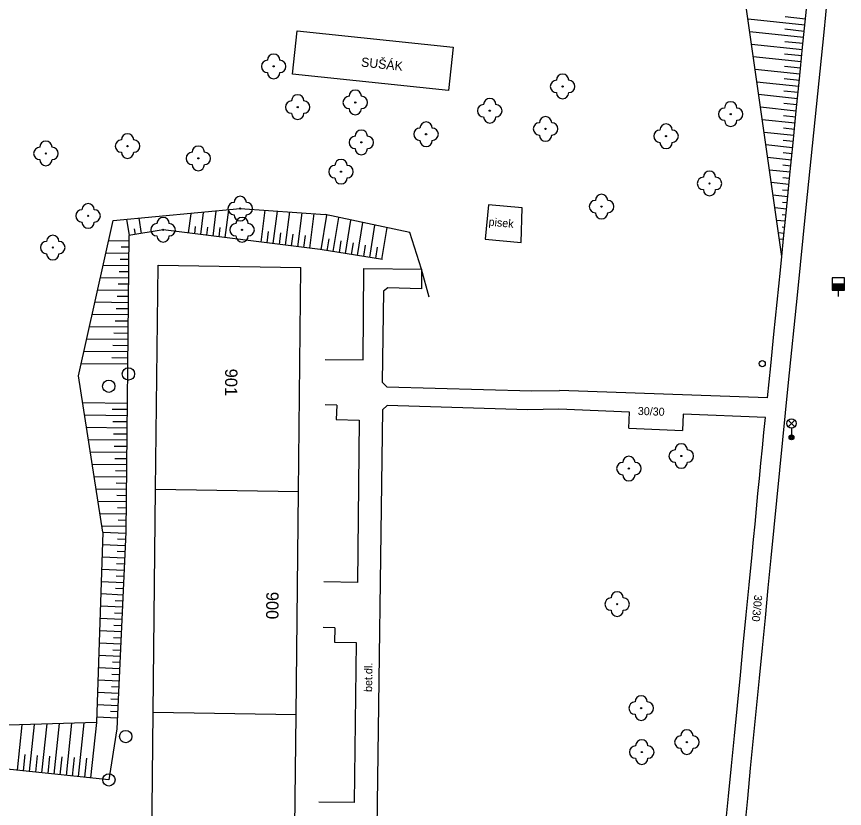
# Model space of a CAD drawing. Extents: x -539244 to -537359, y -1183785 to -1181851.
# Drawn here: x -537476 to -537408.7, y -1182005.8 to -1181941.5 of the extents above; entities that cross this region are included whole.
import ezdxf

# ---------------------------------------------------------------- set-up
doc = ezdxf.new("R2010")
doc.units = 0
for name, color, linetype in [('Vrstva 10', 7, 'Continuous'), ('Vrstva 11', 7, 'Continuous'), ('Vrstva 14', 7, 'Continuous'), ('Vrstva 15', 7, 'Continuous'), ('Vrstva 22', 7, 'Continuous'), ('Vrstva 27', 7, 'Continuous'), ('Vrstva 28', 7, 'Continuous'), ('Vrstva 33', 7, 'Continuous'), ('Vrstva 40', 7, 'Continuous'), ('Vrstva 41', 7, 'Continuous'), ('Vrstva 47', 7, 'Continuous'), ('Vrstva 5', 7, 'Continuous')]:
    doc.layers.add(name, color=color, linetype=linetype)

msp = doc.modelspace()

# ---------------------------------------------------------------- linework, layer by layer
at = {"layer": 'Vrstva 10'}
for p, q in [((-537453.538, -1181946.13), (-537453.17, -1181942.63)), ((-537453.17, -1181942.63), (-537440.512, -1181943.96)), ((-537440.512, -1181943.96), (-537440.88, -1181947.46)), ((-537440.88, -1181947.46), (-537453.538, -1181946.13)), ((-537437.632, -1181956.756), (-537437.89, -1181959.55)), ((-537434.89, -1181957.01), (-537437.632, -1181956.756)), ((-537434.97, -1181959.82), (-537434.89, -1181957.01)), ((-537437.89, -1181959.55), (-537434.97, -1181959.82))]:
    msp.add_line(p, q, dxfattribs=at)
at = {"layer": 'Vrstva 11'}
for p, q in [((-537410.375, -1181942.743), (-537409.65, -1181935.632)), ((-537411.099, -1181949.854), (-537410.375, -1181942.743)), ((-537411.82, -1181956.965), (-537411.099, -1181949.854)), ((-537412.538, -1181964.077), (-537411.82, -1181956.965)), ((-537447.8, -1181969.35), (-537447.76, -1181961.92)), ((-537446.15, -1181963.76), (-537446.26, -1181971.15)), ((-537413.252, -1181971.189), (-537412.538, -1181964.077)), ((-537450.886, -1181969.323), (-537447.8, -1181969.35)), ((-537446.26, -1181971.15), (-537445.88, -1181971.54)), ((-537413.961, -1181978.302), (-537413.252, -1181971.189)), ((-537445.88, -1181971.54), (-537434.11, -1181971.85)), ((-537434.11, -1181971.85), (-537431.866, -1181971.823)), ((-537414.96, -1181972.42), (-537431.866, -1181971.823)), ((-537449.95, -1181973.02), (-537450.908, -1181973.007)), ((-537449.95, -1181973.02), (-537449.99, -1181974.19)), ((-537445.85, -1181973.06), (-537446.25, -1181973.4)), ((-537434.47, -1181973.4), (-537445.85, -1181973.06)), ((-537446.25, -1181973.4), (-537446.83, -1182017.13)), ((-537431.926, -1181973.356), (-537434.47, -1181973.4)), ((-537426.17, -1181973.58), (-537431.926, -1181973.356)), ((-537426.221, -1181974.902), (-537426.17, -1181973.58)), ((-537421.829, -1181973.749), (-537421.88, -1181975.07)), ((-537415.14, -1181974.01), (-537421.829, -1181973.749)), ((-537449.99, -1181974.19), (-537448.13, -1181974.23)), ((-537448.13, -1181974.23), (-537448.28, -1181987.41)), ((-537415.26, -1181975.248), (-537415.14, -1181974.01)), ((-537426.221, -1181974.902), (-537421.88, -1181975.07)), ((-537414.664, -1181985.415), (-537413.961, -1181978.302)), ((-537448.28, -1181987.41), (-537451.004, -1181987.381)), ((-537450.124, -1181991.09), (-537451.057, -1181991.077)), ((-537450.124, -1181991.09), (-537450.14, -1181992.26)), ((-537450.14, -1181992.26), (-537448.369, -1181992.284)), ((-537448.369, -1181992.284), (-537448.542, -1182005.289)), ((-537448.542, -1182005.289), (-537451.42, -1182005.258))]:
    msp.add_line(p, q, dxfattribs=at)
for points in [[(-537412.114, -1181943.958), (-537411.854, -1181941.371), (-537411.64, -1181939.32), (-537411.594, -1181938.783), (-537411.334, -1181936.196), (-537411.073, -1181933.609)], [(-537413.15, -1181954.308), (-537412.892, -1181951.72), (-537412.633, -1181949.133), (-537412.374, -1181946.545), (-537412.114, -1181943.958)], [(-537414.184, -1181964.658), (-537413.926, -1181962.07), (-537413.813, -1181960.94), (-537413.667, -1181959.483), (-537413.409, -1181956.895), (-537413.15, -1181954.308)], [(-537447.76, -1181961.92), (-537443.06, -1181961.98), (-537443.08, -1181963.58), (-537445.81, -1181963.5), (-537446.15, -1181963.76)], [(-537414.96, -1181972.42), (-537414.701, -1181969.833), (-537414.443, -1181967.245), (-537414.184, -1181964.658)], [(-537416.223, -1181985.156), (-537416.103, -1181983.918), (-537415.982, -1181982.679), (-537415.862, -1181981.441), (-537415.742, -1181980.202), (-537415.621, -1181978.964), (-537415.501, -1181977.725), (-537415.381, -1181976.487), (-537415.26, -1181975.248)], [(-537416.461, -1181987.607), (-537416.223, -1181985.156)], [(-537414.904, -1181987.857), (-537414.664, -1181985.415)], [(-537417.413, -1181997.41), (-537417.175, -1181994.959), (-537416.937, -1181992.509), (-537416.699, -1181990.058), (-537416.461, -1181987.607)], [(-537415.862, -1181997.623), (-537415.623, -1181995.182), (-537415.384, -1181992.74), (-537415.144, -1181990.298), (-537414.904, -1181987.857)], [(-537417.652, -1181999.861), (-537417.413, -1181997.41)], [(-537416.1, -1182000.065), (-537415.862, -1181997.623)], [(-537418.611, -1182009.664), (-537418.372, -1182007.213), (-537418.132, -1182004.762), (-537417.892, -1182002.312), (-537417.652, -1181999.861)], [(-537417.048, -1182009.833), (-537416.811, -1182007.391), (-537416.574, -1182004.949), (-537416.337, -1182002.507), (-537416.1, -1182000.065)]]:
    msp.add_lwpolyline(points, dxfattribs=at)
at = {"layer": 'Vrstva 14'}
for p, q in [((-537413.813, -1181960.94), (-537416.94, -1181939.02)), ((-537468.12, -1181958.03), (-537457.8, -1181957.06)), ((-537457.8, -1181957.06), (-537450.9, -1181957.53)), ((-537444.02, -1181958.99), (-537450.9, -1181957.53)), ((-537470.93, -1181970.63), (-537468.12, -1181958.03)), ((-537464.06, -1181958.78), (-537466.836, -1181959.236)), ((-537451.3, -1181960.39), (-537464.06, -1181958.78)), ((-537466.836, -1181959.236), (-537467.08, -1181983.34)), ((-537446.25, -1181961.2), (-537451.3, -1181960.39)), ((-537468.95, -1181983.33), (-537470.93, -1181970.63)), ((-537468.95, -1181983.33), (-537469.48, -1181998.78)), ((-537467.08, -1181983.34), (-537467.81, -1181999.3)), ((-537469.48, -1181998.78), (-537478.65, -1181999.07)), ((-537467.81, -1181999.3), (-537468.46, -1182003.45)), ((-537468.46, -1182003.45), (-537478.76, -1182002.37))]:
    msp.add_line(p, q, dxfattribs=at)
msp.add_lwpolyline([(-537442.46, -1181964.24), (-537443.06, -1181961.98), (-537444.02, -1181958.99)], dxfattribs=at)
at = {"layer": 'Vrstva 15'}
for p, q in [((-537413.545, -1181941.469), (-537411.882, -1181941.644)), ((-537416.552, -1181941.656), (-537411.932, -1181942.141)), ((-537416.399, -1181942.678), (-537412.032, -1181943.137)), ((-537413.559, -1181942.473), (-537411.982, -1181942.639)), ((-537413.573, -1181943.477), (-537412.081, -1181943.634)), ((-537416.273, -1181943.696), (-537412.131, -1181944.132)), ((-537416.127, -1181944.717), (-537412.231, -1181945.127)), ((-537413.588, -1181944.481), (-537412.181, -1181944.629)), ((-537413.602, -1181945.485), (-537412.281, -1181945.624)), ((-537415.982, -1181945.739), (-537412.33, -1181946.122)), ((-537415.836, -1181946.759), (-537412.43, -1181947.117)), ((-537413.616, -1181946.489), (-537412.38, -1181946.62)), ((-537413.63, -1181947.493), (-537412.48, -1181947.614)), ((-537415.69, -1181947.78), (-537412.53, -1181948.112)), ((-537415.545, -1181948.8), (-537412.629, -1181949.107)), ((-537413.645, -1181948.497), (-537412.579, -1181948.61)), ((-537413.659, -1181949.501), (-537412.679, -1181949.604)), ((-537415.399, -1181949.821), (-537412.729, -1181950.102)), ((-537415.253, -1181950.842), (-537412.828, -1181951.097)), ((-537413.673, -1181950.505), (-537412.779, -1181950.6)), ((-537413.688, -1181951.509), (-537412.878, -1181951.594)), ((-537415.108, -1181951.863), (-537412.928, -1181952.092)), ((-537414.962, -1181952.884), (-537413.028, -1181953.087)), ((-537413.702, -1181952.513), (-537412.978, -1181952.59)), ((-537413.716, -1181953.517), (-537413.077, -1181953.584)), ((-537414.817, -1181953.905), (-537413.127, -1181954.082)), ((-537414.671, -1181954.925), (-537413.227, -1181955.077)), ((-537413.73, -1181954.522), (-537413.177, -1181954.58)), ((-537413.745, -1181955.526), (-537413.277, -1181955.574)), ((-537414.525, -1181955.946), (-537413.326, -1181956.073)), ((-537414.38, -1181956.967), (-537413.426, -1181957.067)), ((-537413.759, -1181956.53), (-537413.376, -1181956.57)), ((-537461.82, -1181957.471), (-537462.017, -1181959.038)), ((-537460.799, -1181957.367), (-537461.025, -1181959.163)), ((-537459.778, -1181957.262), (-537460.033, -1181959.288)), ((-537458.756, -1181957.158), (-537459.041, -1181959.413)), ((-537455.801, -1181957.196), (-537456.127, -1181959.781)), ((-537454.802, -1181957.264), (-537455.135, -1181959.906)), ((-537453.803, -1181957.332), (-537454.143, -1181960.031)), ((-537452.803, -1181957.4), (-537453.151, -1181960.156)), ((-537451.804, -1181957.468), (-537452.159, -1181960.282)), ((-537450.8, -1181957.588), (-537451.251, -1181960.398)), ((-537413.773, -1181957.534), (-537413.476, -1181957.564)), ((-537467.04, -1181957.925), (-537466.824, -1181959.234)), ((-537466.041, -1181957.832), (-537465.838, -1181959.072)), ((-537449.82, -1181957.789), (-537450.264, -1181960.556)), ((-537448.839, -1181957.99), (-537449.276, -1181960.715)), ((-537447.859, -1181958.191), (-537448.289, -1181960.873)), ((-537446.878, -1181958.392), (-537447.302, -1181961.031)), ((-537414.234, -1181957.988), (-537413.526, -1181958.063)), ((-537466.404, -1181958.707), (-537466.331, -1181959.153)), ((-537461.447, -1181958.512), (-537461.521, -1181959.1)), ((-537460.445, -1181958.557), (-537460.529, -1181959.225)), ((-537459.443, -1181958.601), (-537459.537, -1181959.351)), ((-537455.516, -1181958.929), (-537455.631, -1181959.843)), ((-537454.521, -1181959.034), (-537454.639, -1181959.969)), ((-537445.898, -1181958.593), (-537446.314, -1181961.19)), ((-537414.088, -1181959.009), (-537413.625, -1181959.057)), ((-537413.787, -1181958.538), (-537413.575, -1181958.56)), ((-537468.482, -1181959.654), (-537466.84, -1181959.671)), ((-537453.527, -1181959.139), (-537453.647, -1181960.094)), ((-537452.532, -1181959.244), (-537452.655, -1181960.219)), ((-537450.601, -1181959.501), (-537450.757, -1181960.477)), ((-537449.616, -1181959.674), (-537449.77, -1181960.635)), ((-537414.015, -1181959.525), (-537413.674, -1181959.552)), ((-537467.457, -1181960.165), (-537466.845, -1181960.171)), ((-537448.631, -1181959.848), (-537448.783, -1181960.794)), ((-537447.646, -1181960.021), (-537447.795, -1181960.952)), ((-537446.661, -1181960.194), (-537446.808, -1181961.111)), ((-537468.705, -1181960.652), (-537466.851, -1181960.671)), ((-537468.927, -1181961.65), (-537466.861, -1181961.671)), ((-537467.542, -1181961.164), (-537466.856, -1181961.171)), ((-537467.626, -1181962.163), (-537466.866, -1181962.171)), ((-537469.15, -1181962.648), (-537466.871, -1181962.671)), ((-537469.372, -1181963.645), (-537466.881, -1181963.671)), ((-537467.711, -1181963.162), (-537466.876, -1181963.171)), ((-537467.795, -1181964.161), (-537466.886, -1181964.171)), ((-537469.595, -1181964.643), (-537466.891, -1181964.671)), ((-537467.88, -1181965.161), (-537466.896, -1181965.171)), ((-537469.817, -1181965.641), (-537466.901, -1181965.671)), ((-537467.964, -1181966.16), (-537466.906, -1181966.171)), ((-537470.04, -1181966.639), (-537466.911, -1181966.67)), ((-537468.049, -1181967.159), (-537466.916, -1181967.17)), ((-537470.262, -1181967.637), (-537466.921, -1181967.67)), ((-537468.133, -1181968.158), (-537466.926, -1181968.17)), ((-537470.485, -1181968.634), (-537466.932, -1181968.67)), ((-537468.217, -1181969.157), (-537466.937, -1181969.17)), ((-537470.707, -1181969.632), (-537466.942, -1181969.67)), ((-537470.59, -1181972.813), (-537466.974, -1181972.849)), ((-537470.434, -1181973.815), (-537466.984, -1181973.849)), ((-537468.201, -1181973.337), (-537466.979, -1181973.349)), ((-537468.147, -1181974.338), (-537466.989, -1181974.349)), ((-537470.277, -1181974.816), (-537466.994, -1181974.849)), ((-537470.121, -1181975.818), (-537467.004, -1181975.849)), ((-537468.094, -1181975.338), (-537466.999, -1181975.349)), ((-537468.04, -1181976.339), (-537467.009, -1181976.349)), ((-537469.965, -1181976.819), (-537467.014, -1181976.849)), ((-537469.809, -1181977.821), (-537467.024, -1181977.849)), ((-537467.987, -1181977.339), (-537467.019, -1181977.349)), ((-537467.933, -1181978.34), (-537467.029, -1181978.349)), ((-537469.653, -1181978.823), (-537467.035, -1181978.849)), ((-537469.497, -1181979.825), (-537467.045, -1181979.849)), ((-537467.88, -1181979.341), (-537467.04, -1181979.349)), ((-537467.826, -1181980.341), (-537467.05, -1181980.349)), ((-537469.34, -1181980.826), (-537467.055, -1181980.849)), ((-537469.184, -1181981.827), (-537467.065, -1181981.849)), ((-537467.773, -1181981.342), (-537467.06, -1181981.349)), ((-537467.719, -1181982.342), (-537467.07, -1181982.349)), ((-537469.028, -1181982.829), (-537467.075, -1181982.849)), ((-537468.95, -1181983.33), (-537467.083, -1181983.415)), ((-537467.758, -1181983.885), (-537467.106, -1181983.915)), ((-537468.984, -1181984.329), (-537467.129, -1181984.414)), ((-537469.019, -1181985.329), (-537467.175, -1181985.413)), ((-537467.799, -1181984.884), (-537467.152, -1181984.914)), ((-537467.841, -1181985.883), (-537467.198, -1181985.913)), ((-537469.053, -1181986.328), (-537467.221, -1181986.412)), ((-537469.087, -1181987.328), (-537467.266, -1181987.411)), ((-537467.883, -1181986.882), (-537467.243, -1181986.912)), ((-537467.924, -1181987.882), (-537467.289, -1181987.911)), ((-537469.121, -1181988.327), (-537467.312, -1181988.41)), ((-537469.156, -1181989.327), (-537467.358, -1181989.409)), ((-537467.966, -1181988.881), (-537467.335, -1181988.91)), ((-537468.008, -1181989.88), (-537467.38, -1181989.909)), ((-537469.19, -1181990.326), (-537467.403, -1181990.408)), ((-537469.224, -1181991.326), (-537467.449, -1181991.407)), ((-537468.049, -1181990.879), (-537467.426, -1181990.908)), ((-537468.091, -1181991.878), (-537467.472, -1181991.906)), ((-537469.259, -1181992.325), (-537467.495, -1181992.406)), ((-537469.293, -1181993.325), (-537467.54, -1181993.405)), ((-537468.133, -1181992.877), (-537467.518, -1181992.905)), ((-537468.175, -1181993.876), (-537467.563, -1181993.904)), ((-537469.327, -1181994.324), (-537467.586, -1181994.404)), ((-537469.361, -1181995.324), (-537467.632, -1181995.403)), ((-537468.216, -1181994.876), (-537467.609, -1181994.903)), ((-537468.258, -1181995.875), (-537467.655, -1181995.902)), ((-537469.396, -1181996.323), (-537467.677, -1181996.402)), ((-537469.43, -1181997.323), (-537467.723, -1181997.401)), ((-537468.3, -1181996.874), (-537467.7, -1181996.901)), ((-537468.341, -1181997.873), (-537467.746, -1181997.9)), ((-537469.48, -1181998.78), (-537469.953, -1182003.293)), ((-537469.464, -1181998.322), (-537467.769, -1181998.4)), ((-537475.533, -1181998.971), (-537475.921, -1182002.668)), ((-537474.524, -1181998.94), (-537474.926, -1182002.772)), ((-537473.515, -1181998.908), (-537473.931, -1182002.876)), ((-537472.506, -1181998.876), (-537472.937, -1182002.981)), ((-537471.498, -1181998.844), (-537471.942, -1182003.085)), ((-537470.489, -1181998.812), (-537470.948, -1182003.189)), ((-537475.285, -1182001.402), (-537475.423, -1182002.72)), ((-537474.286, -1182001.459), (-537474.429, -1182002.824)), ((-537473.286, -1182001.516), (-537473.434, -1182002.928)), ((-537472.286, -1182001.572), (-537472.44, -1182003.033)), ((-537471.287, -1182001.629), (-537471.445, -1182003.137)), ((-537470.287, -1182001.685), (-537470.451, -1182003.241))]:
    msp.add_line(p, q, dxfattribs=at)
at = {"layer": 'Vrstva 22'}
for centre in [(-537455.08, -1181945.51), (-537431.61, -1181947.14), (-537453.13, -1181948.82), (-537448.45, -1181948.44), (-537437.53, -1181949.11), (-537417.96, -1181949.39), (-537442.7, -1181951.02), (-537433, -1181950.59), (-537447.96, -1181951.68), (-537423.21, -1181951.18), (-537466.95, -1181951.98), (-537473.58, -1181952.58), (-537461.2, -1181952.98), (-537449.61, -1181954.06), (-537419.68, -1181955.02), (-537457.8, -1181957.06), (-537428.45, -1181956.9), (-537470.15, -1181957.65), (-537464.06, -1181958.78), (-537457.65, -1181958.78), (-537473.02, -1181960.22), (-537421.97, -1181977.15), (-537426.23, -1181978.17), (-537427.18, -1181989.18), (-537425.23, -1181997.62), (-537421.52, -1182000.38), (-537425.18, -1182001.19)]:
    msp.add_circle(centre, 0.05, dxfattribs=at)
for centre, start, end in [((-537455.08, -1181945.01), 0, 180), ((-537455.58, -1181945.51), 90, 270), ((-537454.58, -1181945.51), 270, 90), ((-537455.08, -1181946.01), 180, 0), ((-537431.61, -1181946.64), 0, 180), ((-537432.11, -1181947.14), 90, 270), ((-537431.11, -1181947.14), 270, 90), ((-537448.45, -1181947.94), 0, 180), ((-537431.61, -1181947.64), 180, 0), ((-537453.63, -1181948.82), 90, 270), ((-537453.13, -1181948.32), 0, 180), ((-537452.63, -1181948.82), 270, 90), ((-537448.95, -1181948.44), 90, 270), ((-537447.95, -1181948.44), 270, 90), ((-537437.53, -1181948.61), 0, 180), ((-537448.45, -1181948.94), 180, 0), ((-537438.03, -1181949.11), 90, 270), ((-537437.03, -1181949.11), 270, 90), ((-537418.46, -1181949.39), 90, 270), ((-537417.96, -1181948.89), 0, 180), ((-537417.46, -1181949.39), 270, 90), ((-537453.13, -1181949.32), 180, 0), ((-537437.53, -1181949.61), 180, 0), ((-537433, -1181950.09), 0, 180), ((-537442.7, -1181950.52), 0, 180), ((-537433.5, -1181950.59), 90, 270), ((-537432.5, -1181950.59), 270, 90), ((-537423.21, -1181950.68), 0, 180), ((-537417.96, -1181949.89), 180, 0), ((-537466.95, -1181951.48), 0, 180), ((-537447.96, -1181951.18), 0, 180), ((-537443.2, -1181951.02), 90, 270), ((-537442.2, -1181951.02), 270, 90), ((-537423.71, -1181951.18), 90, 270), ((-537422.71, -1181951.18), 270, 90), ((-537473.58, -1181952.08), 0, 180), ((-537467.45, -1181951.98), 90, 270), ((-537466.45, -1181951.98), 270, 90), ((-537448.46, -1181951.68), 90, 270), ((-537447.46, -1181951.68), 270, 90), ((-537442.7, -1181951.52), 180, 0), ((-537433, -1181951.09), 180, 0), ((-537423.21, -1181951.68), 180, 0), ((-537474.08, -1181952.58), 90, 270), ((-537473.08, -1181952.58), 270, 90), ((-537461.2, -1181952.48), 0, 180), ((-537447.96, -1181952.18), 180, 0), ((-537466.95, -1181952.48), 180, 0), ((-537461.7, -1181952.98), 90, 270), ((-537460.7, -1181952.98), 270, 90), ((-537449.61, -1181953.56), 0, 180), ((-537473.58, -1181953.08), 180, 0), ((-537461.2, -1181953.48), 180, 0), ((-537450.11, -1181954.06), 90, 270), ((-537449.11, -1181954.06), 270, 90), ((-537419.68, -1181954.52), 0, 180), ((-537449.61, -1181954.56), 180, 0), ((-537420.18, -1181955.02), 90, 270), ((-537419.18, -1181955.02), 270, 90), ((-537419.68, -1181955.52), 180, 0), ((-537457.8, -1181956.56), 0, 180), ((-537428.95, -1181956.9), 90, 270), ((-537428.45, -1181956.4), 0, 180), ((-537427.95, -1181956.9), 270, 90), ((-537470.15, -1181957.15), 0, 180), ((-537458.3, -1181957.06), 90, 270), ((-537457.3, -1181957.06), 270, 90), ((-537470.65, -1181957.65), 90, 270), ((-537469.65, -1181957.65), 270, 90), ((-537464.06, -1181958.28), 0, 180), ((-537457.8, -1181957.56), 180, 0), ((-537457.65, -1181958.28), 0, 180), ((-537428.45, -1181957.4), 180, 0), ((-537470.15, -1181958.15), 180, 0), ((-537464.56, -1181958.78), 90, 270), ((-537463.56, -1181958.78), 270, 90), ((-537458.15, -1181958.78), 90, 270), ((-537457.15, -1181958.78), 270, 90), ((-537473.52, -1181960.22), 90, 270), ((-537473.02, -1181959.72), 0, 180), ((-537472.52, -1181960.22), 270, 90), ((-537464.06, -1181959.28), 180, 0), ((-537457.65, -1181959.28), 180, 0), ((-537473.02, -1181960.72), 180, 0), ((-537421.97, -1181976.65), 0, 180), ((-537426.23, -1181977.67), 0, 180), ((-537422.47, -1181977.15), 90, 270), ((-537421.47, -1181977.15), 270, 90), ((-537426.73, -1181978.17), 90, 270), ((-537425.73, -1181978.17), 270, 90), ((-537421.97, -1181977.65), 180, 0), ((-537426.23, -1181978.67), 180, 0), ((-537427.68, -1181989.18), 90, 270), ((-537427.18, -1181988.68), 0, 180), ((-537426.68, -1181989.18), 270, 90), ((-537427.18, -1181989.68), 180, 0), ((-537425.23, -1181997.12), 0, 180), ((-537425.73, -1181997.62), 90, 270), ((-537424.73, -1181997.62), 270, 90), ((-537425.23, -1181998.12), 180, 0), ((-537421.52, -1181999.88), 0, 180), ((-537422.02, -1182000.38), 90, 270), ((-537421.02, -1182000.38), 270, 90), ((-537425.68, -1182001.19), 90, 270), ((-537425.18, -1182000.69), 0, 180), ((-537424.68, -1182001.19), 270, 90), ((-537421.52, -1182000.88), 180, 0), ((-537425.18, -1182001.69), 180, 0)]:
    msp.add_arc(centre, 0.5, start, end, dxfattribs=at)
at = {"layer": 'Vrstva 27'}
for centre in [(-537466.88, -1181970.49), (-537468.47, -1181971.49), (-537467.1, -1181999.93), (-537468.46, -1182003.45)]:
    msp.add_circle(centre, 0.5, dxfattribs=at)
at = {"layer": 'Vrstva 28'}
for p, q in [((-537409.72, -1181963.18), (-537408.72, -1181963.18)), ((-537409.72, -1181963.23), (-537408.72, -1181963.23)), ((-537409.72, -1181963.28), (-537408.72, -1181963.28)), ((-537409.72, -1181963.33), (-537408.72, -1181963.33)), ((-537409.72, -1181963.38), (-537408.72, -1181963.38)), ((-537409.72, -1181963.43), (-537408.72, -1181963.43)), ((-537409.72, -1181963.48), (-537408.72, -1181963.48)), ((-537409.72, -1181963.53), (-537408.72, -1181963.53)), ((-537409.72, -1181963.58), (-537408.72, -1181963.58)), ((-537409.72, -1181963.63), (-537408.72, -1181963.63)), ((-537409.22, -1181963.68), (-537409.22, -1181964.21))]:
    msp.add_line(p, q, dxfattribs=at)
msp.add_lwpolyline([(-537409.72, -1181963.68), (-537408.72, -1181963.68), (-537408.72, -1181962.68), (-537409.72, -1181962.68)], close=True, dxfattribs=at)
msp.add_circle((-537415.4, -1181969.65), 0.25, dxfattribs=at)
at = {"layer": 'Vrstva 33'}
for p, q in [((-537413.285, -1181974.77), (-537412.755, -1181974.24)), ((-537413.285, -1181974.24), (-537412.755, -1181974.77)), ((-537413.02, -1181974.88), (-537413.02, -1181975.63))]:
    msp.add_line(p, q, dxfattribs=at)
for centre, radius in [((-537413.02, -1181974.505), 0.375), ((-537413.02, -1181975.63), 0.2), ((-537413.02, -1181975.63), 0.145), ((-537413.02, -1181975.63), 0.0876)]:
    msp.add_circle(centre, radius, dxfattribs=at)
at = {"layer": 'Vrstva 5'}
for p, q in [((-537464.667, -1181979.851), (-537464.469, -1181961.642)), ((-537464.469, -1181961.642), (-537452.87, -1181961.83)), ((-537453.066, -1181980.039), (-537452.87, -1181961.83)), ((-537464.667, -1181979.851), (-537453.066, -1181980.039)), ((-537464.863, -1181997.96), (-537453.262, -1181998.148))]:
    msp.add_line(p, q, dxfattribs=at)
for points in [[(-537464.863, -1181997.96), (-537464.667, -1181979.851)], [(-537453.262, -1181998.148), (-537453.066, -1181980.039)], [(-537465.06, -1182016.23), (-537464.863, -1181997.96)], [(-537453.46, -1182016.42), (-537453.262, -1181998.148)]]:
    msp.add_lwpolyline(points, dxfattribs=at)

# ---------------------------------------------------------------- texts
at = {"layer": 'Vrstva 40'}
for s, rotation, p in [('pisek', 354.70762, (-537437.641, -1181958.438)), ('30/30', 357.97756, (-537425.511, -1181973.812)), ('30/30', 264.44963, (-537416.035, -1181988.399)), ('bet.dl.', 89.24012, (-537447.087, -1181996.311))]:
    msp.add_text(s, height=0.65, rotation=rotation, dxfattribs=at).set_placement(p)
at = {"layer": 'Vrstva 41'}
msp.add_text('SUŠÁK', height=0.75, rotation=354.00183, dxfattribs=at).set_placement((-537448.01, -1181945.52))
at = {"layer": 'Vrstva 47'}
for s, p in [(' 901', (-537459.014, -1181969.68)), (' 900', (-537455.67, -1181987.8))]:
    msp.add_text(s, height=1, rotation=269.37971, dxfattribs=at).set_placement(p)

doc.saveas('drawing.dxf')
